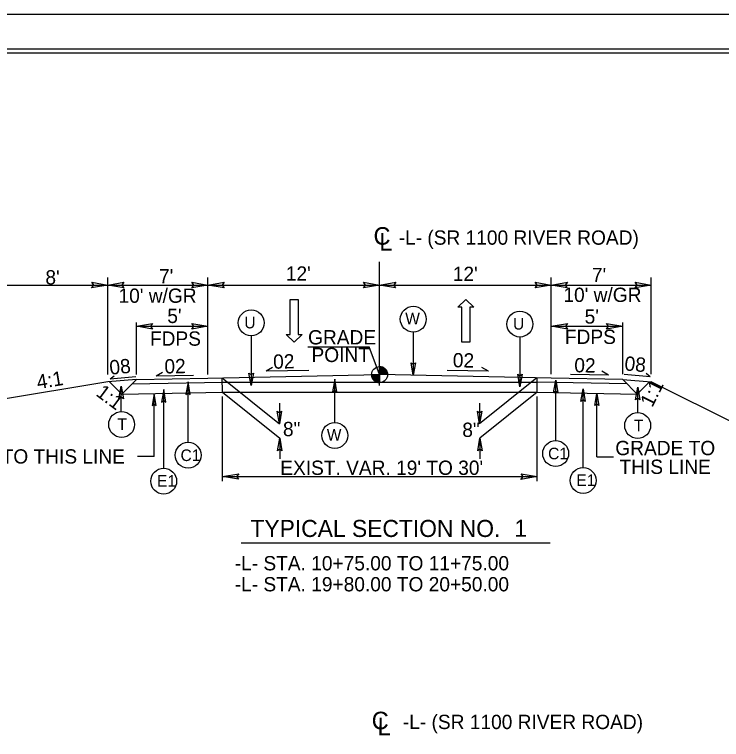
# Model space of a CAD drawing. Extents: x 1734085 to 1734267, y 541107 to 541226.
# Drawn here: x 1734191.6 to 1734241, y 541175.2 to 541225.9 of the extents above; entities that cross this region are included whole.
import ezdxf

# ---------------------------------------------------------------- set-up
doc = ezdxf.new("R2010")
doc.units = 0
for name, color, linetype in [('Prop Dimension', 7, 'Continuous'), ('Prop Lane Arrow CELL', 7, 'Continuous'), ('Prop Terminator CELL', 7, 'Continuous'), ('Sheet Cutting Line CELL', 7, 'Continuous'), ('Sheet Plot Border Inside CELL', 7, 'Continuous'), ('Sheet Plot Border Outside CELL', 7, 'Continuous'), ('Sheet Typical CELL', 7, 'Continuous'), ('Typical Grade Point Symbol CELL', 7, 'Continuous'), ('Typical ID Circle CELL', 7, 'Continuous'), ('Typical Pavement Slope CELL', 7, 'Continuous'), ('Typical Pavement Slope Information CELL', 7, 'Continuous'), ('Typical Shoulder Slope CELL', 7, 'Continuous'), ('Typical Shoulder Slope Information CELL', 7, 'Continuous'), ('Typical Slope Point Local CELL', 7, 'Continuous'), ('Typical Terminator CELL', 7, 'Continuous'), ('Typical Text Centerline CELL', 7, 'Continuous'), ('Typical Text General CELL', 7, 'Continuous'), ('Typical Text Grade Point CELL', 7, 'Continuous'), ('Typical Text ID Circle CELL', 7, 'Continuous'), ('Typical Text Label CELL', 7, 'Continuous')]:
    doc.layers.add(name, color=color, linetype=linetype)

msp = doc.modelspace()

# ---------------------------------------------------------------- linework, layer by layer
at = {"layer": 'Prop Dimension'}
for p, q in [((1734217.135, 541199.924), (1734217.135, 541208.57)), ((1734198.135, 541200.683), (1734198.135, 541207.476)), ((1734205.135, 541200.683), (1734205.135, 541207.476)), ((1734229.135, 541200.71), (1734229.135, 541207.476)), ((1734236.135, 541200.71), (1734236.135, 541207.476)), ((1734190.135, 541206.953), (1734198.135, 541206.953)), ((1734198.135, 541206.953), (1734205.135, 541206.953)), ((1734205.135, 541206.953), (1734217.135, 541206.953)), ((1734217.135, 541206.953), (1734229.135, 541206.953)), ((1734229.135, 541206.953), (1734236.135, 541206.953)), ((1734200.13, 541200.682), (1734200.13, 541204.32)), ((1734200.13, 541204.07), (1734205.13, 541204.07)), ((1734229.139, 541204.07), (1734234.135, 541204.07)), ((1734234.135, 541200.71), (1734234.135, 541204.32)), ((1734212.128, 541202.62), (1734216.4, 541202.62)), ((1734217.135, 541200.683), (1734216.4, 541202.62)), ((1734206.135, 541200.463), (1734210.136, 541197.239)), ((1734228.135, 541200.463), (1734224.134, 541197.239)), ((1734206.155, 541200.162), (1734228.155, 541200.162)), ((1734228.155, 541199.462), (1734228.155, 541200.143)), ((1734206.155, 541199.463), (1734228.155, 541199.462)), ((1734206.155, 541199.463), (1734210.156, 541196.24)), ((1734228.155, 541199.462), (1734224.154, 541196.239)), ((1734206.155, 541193.241), (1734206.155, 541199.146)), ((1734228.155, 541193.241), (1734228.155, 541199.146)), ((1734210.136, 541198.692), (1734210.136, 541197.239)), ((1734224.134, 541198.692), (1734224.134, 541197.239)), ((1734210.156, 541196.24), (1734210.156, 541194.787)), ((1734224.154, 541196.239), (1734224.154, 541194.786)), ((1734201.378, 541194.947), (1734200.206, 541194.947)), ((1734232.325, 541194.946), (1734233.498, 541194.946)), ((1734206.155, 541193.555), (1734228.155, 541193.555))]:
    msp.add_line(p, q, dxfattribs=at)
at = {"layer": 'Prop Lane Arrow CELL'}
for p, q in [((1734210.874, 541203.499), (1734210.874, 541205.949)), ((1734210.874, 541205.949), (1734211.451, 541205.949)), ((1734211.451, 541205.949), (1734211.451, 541203.499)), ((1734222.618, 541205.397), (1734223.161, 541205.948)), ((1734223.161, 541205.948), (1734223.721, 541205.397)), ((1734222.881, 541205.397), (1734222.618, 541205.397)), ((1734222.881, 541202.947), (1734222.881, 541205.397)), ((1734223.721, 541205.397), (1734223.458, 541205.397)), ((1734223.458, 541205.397), (1734223.458, 541202.947)), ((1734211.171, 541202.948), (1734210.611, 541203.499)), ((1734210.611, 541203.499), (1734210.874, 541203.499)), ((1734211.714, 541203.499), (1734211.171, 541202.948)), ((1734211.451, 541203.499), (1734211.714, 541203.499)), ((1734223.458, 541202.947), (1734222.881, 541202.947))]:
    msp.add_line(p, q, dxfattribs=at)
at = {"layer": 'Prop Terminator CELL'}
for points in [[(1734197.01, 541207.147), (1734198.135, 541206.953), (1734197.003, 541206.753), (1734197.147, 541206.953)], [(1734199.26, 541206.759), (1734198.135, 541206.953), (1734199.266, 541207.153), (1734199.122, 541206.953)], [(1734204.01, 541207.147), (1734205.135, 541206.953), (1734204.003, 541206.753), (1734204.147, 541206.953)], [(1734206.26, 541206.759), (1734205.135, 541206.953), (1734206.266, 541207.153), (1734206.122, 541206.953)], [(1734216.01, 541207.147), (1734217.135, 541206.953), (1734216.003, 541206.753), (1734216.147, 541206.953)], [(1734218.26, 541206.759), (1734217.135, 541206.953), (1734218.266, 541207.153), (1734218.122, 541206.953)], [(1734228.01, 541207.147), (1734229.135, 541206.953), (1734228.003, 541206.753), (1734228.147, 541206.953)], [(1734230.26, 541206.759), (1734229.135, 541206.953), (1734230.266, 541207.153), (1734230.122, 541206.953)], [(1734235.01, 541207.147), (1734236.135, 541206.953), (1734235.003, 541206.753), (1734235.147, 541206.953)], [(1734201.255, 541203.876), (1734200.13, 541204.07), (1734201.262, 541204.27), (1734201.118, 541204.07)], [(1734204.005, 541204.264), (1734205.13, 541204.07), (1734203.999, 541203.87), (1734204.143, 541204.07)], [(1734230.264, 541203.876), (1734229.139, 541204.07), (1734230.27, 541204.27), (1734230.127, 541204.07)], [(1734233.01, 541204.264), (1734234.135, 541204.07), (1734233.003, 541203.87), (1734233.147, 541204.07)], [(1734201.524, 541198.525), (1734201.378, 541199.369), (1734201.228, 541198.521), (1734201.378, 541198.628)], [(1734232.18, 541198.524), (1734232.325, 541199.368), (1734232.475, 541198.519), (1734232.325, 541198.627)], [(1734207.28, 541193.361), (1734206.155, 541193.555), (1734207.286, 541193.755), (1734207.142, 541193.555)], [(1734227.03, 541193.749), (1734228.155, 541193.555), (1734227.023, 541193.355), (1734227.167, 541193.555)]]:
    msp.add_lwpolyline(points, close=True, dxfattribs=at)
at = {"layer": 'Sheet Cutting Line CELL'}
msp.add_line((1734266.513, 541225.875), (1734084.641, 541225.875), dxfattribs=at)
at = {"layer": 'Sheet Plot Border Inside CELL'}
msp.add_lwpolyline([(1734266.027, 541223.451), (1734086.045, 541223.451), (1734086.045, 541109.5), (1734266.027, 541109.5)], close=True, dxfattribs=at)
at = {"layer": 'Sheet Plot Border Outside CELL'}
msp.add_lwpolyline([(1734266.513, 541225.875), (1734084.641, 541225.875), (1734084.641, 541107.075), (1734266.513, 541107.075)], close=True, dxfattribs=at)
at = {"layer": 'Sheet Typical CELL'}
msp.add_lwpolyline([(1734264.677, 541223.175), (1734102.677, 541223.175), (1734102.677, 541109.775), (1734264.677, 541109.775)], close=True, dxfattribs=at)
at = {"layer": 'Typical Grade Point Symbol CELL'}
for p, q in [((1734217.135, 541200.683), (1734217.135, 541201.242)), ((1734216.575, 541200.683), (1734217.135, 541200.683)), ((1734217.133, 541200.123), (1734217.135, 541200.683)), ((1734217.135, 541200.683), (1734217.133, 541200.123)), ((1734217.694, 541200.683), (1734217.135, 541200.683))]:
    msp.add_line(p, q, dxfattribs=at)
for points in [[(1734217.14, 541201.242), (1734217.14, 541201.242), (1734217.14, 541200.683)], [(1734217.151, 541201.242), (1734217.151, 541200.683)], [(1734217.162, 541201.241), (1734217.162, 541200.683)], [(1734217.173, 541201.241), (1734217.173, 541200.683)], [(1734217.184, 541201.24), (1734217.184, 541200.683)], [(1734217.196, 541201.238), (1734217.196, 541200.683)], [(1734217.207, 541201.237), (1734217.207, 541200.683)], [(1734217.218, 541201.236), (1734217.218, 541200.683)], [(1734217.229, 541201.235), (1734217.229, 541200.683)], [(1734217.24, 541201.232), (1734217.24, 541200.683)], [(1734217.252, 541201.23), (1734217.252, 541200.683)], [(1734217.263, 541201.227), (1734217.263, 541200.683)], [(1734217.274, 541201.225), (1734217.274, 541200.683)], [(1734217.285, 541201.221), (1734217.285, 541200.683)], [(1734217.296, 541201.218), (1734217.296, 541200.683)], [(1734217.308, 541201.215), (1734217.308, 541200.683)], [(1734217.319, 541201.211), (1734217.319, 541200.683)], [(1734217.33, 541201.207), (1734217.33, 541200.683)], [(1734217.341, 541201.202), (1734217.341, 541200.683)], [(1734217.352, 541201.197), (1734217.352, 541200.683)], [(1734217.364, 541201.192), (1734217.364, 541200.683)], [(1734217.375, 541201.187), (1734217.375, 541200.683)], [(1734217.386, 541201.182), (1734217.386, 541200.683)], [(1734217.397, 541201.176), (1734217.397, 541200.683)], [(1734217.408, 541201.17), (1734217.408, 541200.683)], [(1734217.419, 541201.164), (1734217.419, 541200.683)], [(1734217.431, 541201.158), (1734217.431, 541200.683)], [(1734217.442, 541201.15), (1734217.442, 541200.683)], [(1734217.453, 541201.143), (1734217.453, 541200.683)], [(1734217.464, 541201.134), (1734217.464, 541200.683)], [(1734217.475, 541201.126), (1734217.475, 541200.683)], [(1734217.487, 541201.118), (1734217.487, 541200.683)], [(1734217.498, 541201.108), (1734217.498, 541200.683)], [(1734217.509, 541201.098), (1734217.509, 541200.683)], [(1734217.52, 541201.088), (1734217.52, 541200.683)], [(1734217.531, 541201.077), (1734217.531, 541200.683)], [(1734217.543, 541201.066), (1734217.543, 541200.683)], [(1734217.554, 541201.053), (1734217.554, 541200.683)], [(1734217.565, 541201.039), (1734217.565, 541200.683)], [(1734217.576, 541201.026), (1734217.576, 541200.683)], [(1734217.587, 541201.011), (1734217.587, 541200.683)], [(1734217.599, 541200.995), (1734217.599, 541200.683)], [(1734217.61, 541200.977), (1734217.61, 541200.683)], [(1734217.621, 541200.959), (1734217.621, 541200.683)], [(1734216.578, 541200.683), (1734216.578, 541200.622)], [(1734216.589, 541200.683), (1734216.589, 541200.556)], [(1734216.6, 541200.683), (1734216.6, 541200.516)], [(1734216.611, 541200.683), (1734216.611, 541200.482)], [(1734216.623, 541200.683), (1734216.623, 541200.456)], [(1734216.634, 541200.683), (1734216.634, 541200.433)], [(1734216.645, 541200.683), (1734216.645, 541200.412)], [(1734216.656, 541200.683), (1734216.656, 541200.392)], [(1734216.667, 541200.683), (1734216.667, 541200.374)], [(1734216.678, 541200.683), (1734216.678, 541200.358)], [(1734216.69, 541200.683), (1734216.69, 541200.343)], [(1734216.701, 541200.683), (1734216.701, 541200.329)], [(1734216.712, 541200.683), (1734216.712, 541200.316)], [(1734216.723, 541200.683), (1734216.723, 541200.303)], [(1734216.734, 541200.683), (1734216.734, 541200.291)], [(1734216.746, 541200.683), (1734216.746, 541200.28)], [(1734216.757, 541200.683), (1734216.757, 541200.27)], [(1734216.768, 541200.683), (1734216.768, 541200.26)], [(1734216.779, 541200.683), (1734216.779, 541200.25)], [(1734216.79, 541200.683), (1734216.79, 541200.241)], [(1734216.802, 541200.683), (1734216.802, 541200.233)], [(1734216.813, 541200.683), (1734216.813, 541200.225)], [(1734216.824, 541200.683), (1734216.824, 541200.218)], [(1734216.835, 541200.683), (1734216.835, 541200.21)], [(1734216.846, 541200.683), (1734216.846, 541200.203)], [(1734216.857, 541200.683), (1734216.857, 541200.196)], [(1734216.869, 541200.683), (1734216.869, 541200.19)], [(1734216.88, 541200.683), (1734216.88, 541200.184)], [(1734216.891, 541200.683), (1734216.891, 541200.179)], [(1734216.902, 541200.683), (1734216.902, 541200.174)], [(1734216.913, 541200.683), (1734216.913, 541200.169)], [(1734216.925, 541200.683), (1734216.925, 541200.164)], [(1734216.936, 541200.683), (1734216.936, 541200.159)], [(1734216.947, 541200.683), (1734216.947, 541200.155)], [(1734216.958, 541200.683), (1734216.958, 541200.152)], [(1734216.969, 541200.683), (1734216.969, 541200.148)], [(1734216.981, 541200.683), (1734216.981, 541200.145)], [(1734216.992, 541200.683), (1734216.992, 541200.142)], [(1734217.003, 541200.683), (1734217.003, 541200.139)], [(1734217.014, 541200.683), (1734217.014, 541200.137)], [(1734217.025, 541200.683), (1734217.025, 541200.134)], [(1734217.036, 541200.683), (1734217.036, 541200.132)], [(1734217.048, 541200.683), (1734217.048, 541200.131)], [(1734217.059, 541200.683), (1734217.059, 541200.128)], [(1734217.07, 541200.683), (1734217.07, 541200.127)], [(1734217.081, 541200.683), (1734217.081, 541200.126)], [(1734217.092, 541200.683), (1734217.092, 541200.124)], [(1734217.104, 541200.683), (1734217.104, 541200.124)], [(1734217.115, 541200.683), (1734217.115, 541200.123)], [(1734217.126, 541200.683), (1734217.126, 541200.123), (1734217.126, 541200.123)], [(1734217.632, 541200.939), (1734217.632, 541200.683)], [(1734217.643, 541200.915), (1734217.643, 541200.683)], [(1734217.654, 541200.889), (1734217.654, 541200.683)], [(1734217.666, 541200.858), (1734217.666, 541200.683)], [(1734217.677, 541200.819), (1734217.677, 541200.683)], [(1734217.688, 541200.762), (1734217.688, 541200.683)]]:
    msp.add_lwpolyline(points, dxfattribs=at)
msp.add_circle((1734217.134, 541200.683), 0.559, dxfattribs=at)
for start, end in [(359.9905, 89.9905), (179.9905, 269.9905)]:
    msp.add_arc((1734217.134, 541200.683), 0.559, start, end, dxfattribs=at)
at = {"layer": 'Typical ID Circle CELL'}
for p, q in [((1734219.493, 541203.656), (1734219.493, 541200.636)), ((1734208.16, 541203.396), (1734208.16, 541199.914)), ((1734226.949, 541203.316), (1734226.949, 541199.834)), ((1734203.748, 541195.951), (1734203.748, 541200.178)), ((1734214.007, 541197.336), (1734214.007, 541200.356)), ((1734229.449, 541196.073), (1734229.449, 541200.298)), ((1734199.068, 541198.102), (1734199.068, 541199.882)), ((1734202.043, 541194.139), (1734202.043, 541199.644)), ((1734231.365, 541194.186), (1734231.365, 541199.692)), ((1734235.181, 541198.029), (1734235.181, 541199.808)), ((1734201.378, 541194.947), (1734201.378, 541199.369)), ((1734232.325, 541194.946), (1734232.325, 541199.368))]:
    msp.add_line(p, q, dxfattribs=at)
for centre in [(1734208.16, 541204.303), (1734219.493, 541204.563), (1734226.949, 541204.222), (1734199.101, 541197.197), (1734235.181, 541197.123), (1734214.007, 541196.43), (1734203.748, 541195.045), (1734229.449, 541195.167), (1734202.043, 541193.232), (1734231.365, 541193.279)]:
    msp.add_circle(centre, 0.906, dxfattribs=at)
at = {"layer": 'Typical Pavement Slope CELL'}
for p, q in [((1734205.135, 541200.443), (1734217.135, 541200.683)), ((1734206.155, 541199.463), (1734206.135, 541200.463)), ((1734229.135, 541200.443), (1734217.135, 541200.683)), ((1734228.155, 541199.462), (1734228.155, 541200.462)), ((1734200.13, 541200.34), (1734198.13, 541200.173)), ((1734234.135, 541200.34), (1734236.135, 541200.173)), ((1734199.112, 541199.322), (1734206.155, 541199.463)), ((1734228.155, 541199.462), (1734235.153, 541199.322))]:
    msp.add_line(p, q, dxfattribs=at)
at = {"layer": 'Typical Pavement Slope Information CELL'}
for p, q in [((1734209.202, 541200.939), (1734209.639, 541201.203)), ((1734209.202, 541200.939), (1734212.193, 541200.999)), ((1734224.745, 541200.917), (1734221.851, 541200.975)), ((1734224.745, 541200.917), (1734224.296, 541201.189)), ((1734198.293, 541200.394), (1734198.585, 541200.599)), ((1734198.293, 541200.394), (1734200.101, 541200.556)), ((1734201.518, 541200.596), (1734201.956, 541200.86)), ((1734201.518, 541200.596), (1734204.118, 541200.648)), ((1734233.133, 541200.646), (1734230.493, 541200.699)), ((1734233.133, 541200.646), (1734232.684, 541200.918)), ((1734236.066, 541200.542), (1734234.228, 541200.697)), ((1734236.066, 541200.542), (1734235.765, 541200.752))]:
    msp.add_line(p, q, dxfattribs=at)
at = {"layer": 'Typical Shoulder Slope CELL'}
for p, q in [((1734200.13, 541200.34), (1734205.135, 541200.443)), ((1734234.135, 541200.34), (1734229.135, 541200.443)), ((1734198.25, 541200.183), (1734199.112, 541199.321)), ((1734200.13, 541200.34), (1734199.112, 541199.321)), ((1734199.824, 541200.034), (1734206.155, 541200.163)), ((1734234.441, 541200.034), (1734228.155, 541200.163)), ((1734234.135, 541200.34), (1734235.153, 541199.321)), ((1734236.015, 541200.183), (1734235.153, 541199.321))]:
    msp.add_line(p, q, dxfattribs=at)
at = {"layer": 'Typical Slope Point Local CELL'}
for p, q in [((1734198.13, 541200.173), (1734190.13, 541198.84)), ((1734251.133, 541192.674), (1734236.135, 541200.173))]:
    msp.add_line(p, q, dxfattribs=at)
at = {"layer": 'Typical Terminator CELL'}
for points in [[(1734219.644, 541201.515), (1734219.493, 541200.636), (1734219.337, 541201.52), (1734219.493, 541201.407)], [(1734208.312, 541200.793), (1734208.16, 541199.914), (1734208.004, 541200.798), (1734208.16, 541200.686)], [(1734227.1, 541200.713), (1734226.949, 541199.834), (1734226.793, 541200.718), (1734226.949, 541200.605)], [(1734203.9, 541199.299), (1734203.748, 541200.178), (1734203.592, 541199.294), (1734203.748, 541199.407)], [(1734214.159, 541199.478), (1734214.007, 541200.356), (1734213.851, 541199.473), (1734214.007, 541199.585)], [(1734229.298, 541199.419), (1734229.449, 541200.298), (1734229.605, 541199.414), (1734229.449, 541199.526)], [(1734198.917, 541199.003), (1734199.068, 541199.882), (1734199.224, 541198.998), (1734199.068, 541199.111)], [(1734202.195, 541198.766), (1734202.043, 541199.644), (1734201.887, 541198.761), (1734202.043, 541198.873)], [(1734231.213, 541198.813), (1734231.365, 541199.692), (1734231.521, 541198.808), (1734231.365, 541198.92)], [(1734235.03, 541198.93), (1734235.181, 541199.808), (1734235.337, 541198.925), (1734235.181, 541199.037)], [(1734210.287, 541198.118), (1734210.136, 541197.239), (1734209.98, 541198.123), (1734210.136, 541198.011)], [(1734224.285, 541198.118), (1734224.134, 541197.239), (1734223.977, 541198.123), (1734224.134, 541198.011)], [(1734210.005, 541195.361), (1734210.156, 541196.24), (1734210.312, 541195.356), (1734210.156, 541195.468)], [(1734224.002, 541195.36), (1734224.154, 541196.239), (1734224.31, 541195.355), (1734224.154, 541195.467)]]:
    msp.add_lwpolyline(points, close=True, dxfattribs=at)
at = {"layer": 'Typical Text Label CELL'}
msp.add_line((1734207.469, 541188.929), (1734229.073, 541188.929), dxfattribs=at)

# ---------------------------------------------------------------- texts
at = {"layer": 'Typical Pavement Slope Information CELL'}
for rotation, p in [(1.1457, (1734209.703, 541201.094)), (358.8543, (1734222.248, 541201.202))]:
    msp.add_text('02', height=1, rotation=rotation, dxfattribs=at).set_placement(p)
at = {"layer": 'Typical Shoulder Slope Information CELL'}
for s, rotation, p in [('08', 355.1872, (1734234.232, 541200.982)), ('08', 5.1049, (1734198.293, 541200.68)), ('02', 1.1457, (1734202.103, 541200.76)), ('02', 358.8543, (1734230.742, 541200.852))]:
    msp.add_text(s, height=1, rotation=rotation, dxfattribs=at).set_placement(p)
at = {"layer": 'Typical Slope Point Local CELL'}
for s, rotation, p in [("7'", 360, (1734201.715, 541207.067)), ("12'", 360, (1734210.581, 541207.257)), ("12'", 360, (1734222.255, 541207.231)), ("7'", 360, (1734231.982, 541207.154)), ("8'", 360, (1734193.772, 541206.991)), ("10' w/GR", 360, (1734198.885, 541205.708)), ("10' w/GR", 360, (1734229.989, 541205.768)), ("5'", 360, (1734202.294, 541204.294)), ("5'", 360, (1734231.473, 541204.252)), ('FDPS', 360, (1734201.08, 541202.707)), ('FDPS', 360, (1734230.094, 541202.831)), ('4:1', 9.4623, (1734193.249, 541199.664)), ('1:1', 63.4349, (1734236.201, 541198.342)), ('1:1', 323.3821, (1734197.24, 541199.262)), ('8"', 360, (1734210.379, 541196.379)), ('8"', 360, (1734222.92, 541196.326)), ("EXIST. VAR. 19' TO 30'", 360, (1734210.191, 541193.671))]:
    msp.add_text(s, height=1, rotation=rotation, dxfattribs=at).set_placement(p)
at = {"layer": 'Typical Text Centerline CELL'}
for s, height, p in [('C', 1.23, (1734216.711, 541209.77)), ('-L- (SR 1100 RIVER ROAD)', 1, (1734218.47, 541209.772)), ('C', 1.23, (1734216.586, 541175.875)), ('-L- (SR 1100 RIVER ROAD)', 1, (1734218.763, 541175.892))]:
    msp.add_text(s, height=height, dxfattribs=at).set_placement(p)
for p in [(1734217.12, 541209.35), (1734216.995, 541175.455)]:
    msp.add_text('L', height=1.231, rotation=359.9469, dxfattribs=at).set_placement(p)
at = {"layer": 'Typical Text General CELL'}
for s, p in [('GRADE TO', (1734233.618, 541195.05)), ('GRADE TO THIS LINE', (1734185.587, 541194.463)), ('THIS LINE', (1734233.909, 541193.739))]:
    msp.add_text(s, height=1, dxfattribs=at).set_placement(p)
at = {"layer": 'Typical Text Grade Point CELL'}
for s, p in [('GRADE', (1734212.137, 541202.797)), ('POINT', (1734212.375, 541201.566))]:
    msp.add_text(s, height=1, dxfattribs=at).set_placement(p)
at = {"layer": 'Typical Text ID Circle CELL'}
for s, height, p in [('W', 0.811, (1734218.932, 541204.203)), ('U', 0.811, (1734207.679, 541203.92)), ('U', 0.811, (1734226.467, 541203.839)), ('T', 0.811, (1734198.808, 541196.806)), ('T', 0.811, (1734234.914, 541196.717)), ('W', 0.811, (1734213.446, 541196.07)), ('C1', 0.8112, (1734203.22, 541194.639)), ('C1', 0.8112, (1734228.92, 541194.761)), ('E1', 0.8112, (1734201.578, 541192.842)), ('E1', 0.8112, (1734230.899, 541192.889))]:
    msp.add_text(s, height=height, dxfattribs=at).set_placement(p)
at = {"layer": 'Typical Text Label CELL'}
for s, height, p in [('TYPICAL SECTION NO.  ', 1.19356, (1734208.109, 541189.329)), ('1', 1.194, (1734226.562, 541189.345)), ('-L- STA. 10+75.00 TO 11+75.00', 1, (1734207.007, 541186.992)), ('-L- STA. 19+80.00 TO 20+50.00', 1, (1734207.007, 541185.524))]:
    msp.add_text(s, height=height, dxfattribs=at).set_placement(p)

doc.saveas('drawing.dxf')
